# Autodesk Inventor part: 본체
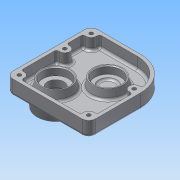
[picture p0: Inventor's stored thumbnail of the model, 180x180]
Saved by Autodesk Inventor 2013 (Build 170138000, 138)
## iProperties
Created: 2015-11
Part Number: 본체
Material: 알루미늄 6061
Document SubType Name: Modeling
Designer: Administrator
Density: 2.71 g/cm^3
Mass: 247.293 g
Surface Area: 390.248 cm^2
Volume: 91.2522 cm^3
Author: Administrator
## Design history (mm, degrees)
sketch "스케치1"
  geometry: L1 (-60, 40)-(-60, -63); L2 (-60, -63)-(40, -63); L3 (40, -63)-(40, 0); L4 (0, 40)-(-60, 40); A1 r 40 centre (0, 0) between (40, 0) and (0, 40); 1 further point
  constraints: 8 end point, 2 coincident, 2 parallel, 2 point on circle, 2 tangent, 1 centre point, 1 perpendicular, 1 vertical
  dimensions: "d0" = 103 distance between parallel lines of L2 L4; "d2" = 40 radius of A1; "d3" = 100 distance of L1.end L2.end
extrude "돌출1" new body sketch "스케치1" distance "d4" = 4; taper "d5" = 0 deg
fillet "모깎기1" dims "d6" = 8
sketch "스케치4"
  geometry: L1 (40, -55)-(40, 0) reference; L2 (0, 40)-(-52, 40) reference; L3 (-60, 32)-(-60, -55) reference; L4 (-52, -63)-(32, -63) reference; L5 (-47.528, 36)-(0, 36); L6 (36, -4.472)-(36, -50.528); L7 (27.528, -59)-(-47.528, -59); L8 (-56, -50.528)-(-56, -4.472); L9 (-56, 4.472)-(-56, 27.528); A1 r 8 centre (32, -55) between (32, -63) and (40, -55) reference; A2 r 40 centre (0, 0) between (40, 0) and (0, 40) reference; A3 r 8 centre (-52, 32) between (-52, 40) and (-60, 32) reference; A4 r 8 centre (-52, -55) between (-60, -55) and (-52, -63) reference; A5 r 36 centre (0, 0) between (35.688, 4.733) and (0, 36); A6 r 6 centre (-52, 32) between (-56, 27.528) and (-47.528, 36); A7 r 6 centre (-52, -55) between (-47.528, -59) and (-56, -50.528); A8 r 6 centre (-52, 0) between (-56, -4.472) and (-56, 4.472); A9 r 6 centre (32, 0) between (35.688, 4.733) and (36, -4.472); A10 r 6 centre (32, -55) between (36, -50.528) and (27.528, -59)
  constraints: 12 point on circle, 10 end point, 6 centre point, 4 coincident, 2 concentric, 2 horizontal alignment, 2 vertical alignment
  dimensions: "d17" = 4 distance between parallel lines of L2 L5; "d18" = 4 distance between parallel lines of L4 L7; "d20" = 12 diameter of A6; "d21" = 12 diameter of A7; "d22" = 12 diameter of A10; "d23" = 12 diameter of A9; "d24" = 12 diameter of A8; "d25" = 84 distance of A9.centre A8.centre; "d26" = 36 radius of A5; "d28" = 4 distance between parallel lines of L1 L6; "d29" = 4 distance between parallel lines of L3 L8; "d30" = 4 distance between parallel lines of L3 L9
extrude "돌출2" join sketch "스케치4" distance "d31" = 14; taper "d32" = 0 deg
sketch "스케치5"
  geometry: C1 r 20 at (0, 0); A1 r 36 centre (0, 0) between (35.688, 4.733) and (0, 36) reference
  constraints: 2 coincident, 1 centre point
  dimensions: "d33" = 40 diameter of C1
extrude "돌출3" join sketch "스케치5" distance "d35" = 11; taper "d36" = -10 deg
sketch "스케치7"
  geometry: C1 r 18.06 at (0, 0) reference; C2 r 16 at (0, 0)
  constraints: 2 coincident, 1 centre point
  dimensions: "d44" = 32 diameter of C2
extrude "돌출4" cut sketch "스케치7" distance "d46" = 9; taper "d47" = 0 deg
sketch "스케치8"
  geometry: C1 r 16 at (0, 0) reference; C2 r 11 at (0, 0)
  constraints: 1 centre point, 1 coincident
  dimensions: "d48" = 22 diameter of C2
extrude "돌출5" cut sketch "스케치8" distance "d50" = 2; taper "d51" = 0 deg
sketch "스케치10"
  geometry: L1 (52, -63)-(-32, -63) reference; L2 (60, 32)-(60, -55) reference; C1 r 25 at (30, -33)
  constraints: 1 centre point
  dimensions: "d55" = 30 distance from line of C1.centre L2; "d56" = 30 distance from line of L1 C1.centre; "d57" = 50 diameter of C1
extrude "돌출6" join sketch "스케치10" distance "d58" = 15; taper "d59" = -10 deg
sketch "스케치11"
  geometry: C1 r 22.355 at (0, 0) reference; 2 further points
  constraints: 1 coincident
hole "구멍2" sketch "스케치11" at (0, 0) diameter "d60" = 24; stored, may be unused: countersink angle "d64" = 90 deg, drill point angle "d66" = 0 deg; dims "d61" = 6, "d62" = 28, "d63" = 11, "d65" = 13
sketch "스케치13"
  geometry: L1 (-60, 32)-(-60, -55) reference; L2 (-52, -63)-(32, -63) reference; C1 r 20 at (-30, -33)
  constraints: 1 centre point
  dimensions: "d71" = 30 distance from line of L1 C1.centre; "d72" = 30 distance from line of C1.centre L2; "d73" = 40 diameter of C1
extrude "돌출8" join sketch "스케치13" distance "d74" = 11; taper "d75" = -10 deg
sketch "스케치16"
  geometry: C1 r 18.06 at (0, 0) reference; 2 further points
  constraints: 1 coincident
hole "구멍3" sketch "스케치16" at (0, 0) diameter "d79" = 20; stored, may be unused: countersink angle "d83" = 90 deg, drill point angle "d85" = 0 deg; dims "d80" = 6, "d81" = 32, "d82" = 9, "d84" = 20
sketch "스케치18"
  geometry: L1 (52, -63)-(-32, -63) reference; C1 r 4 at (52, 32); C2 r 4 at (52, 0); C3 r 4 at (52, -55); C4 r 4 at (-32, -55); C5 r 4 at (-32, 0); A1 r 8 centre (-32, -55) between (-40, -55) and (-32, -63) reference; A2 r 8 centre (52, 32) between (60, 32) and (52, 40) reference
  constraints: 5 centre point, 3 vertical alignment, 2 coincident, 1 horizontal alignment
  dimensions: "d88" = 8 diameter of C5; "d90" = 8 diameter of C4; "d91" = 8 diameter of C3; "d92" = 8 diameter of C2; "d93" = 8 diameter of C1; "d94" = 8 distance from line of C3.centre L1; "d95" = 63 distance from line of L1 C5.centre
extrude "돌출10" cut sketch "스케치18" distance "d96" = 4.4; taper "d97" = 0 deg
sketch "스케치19"
  geometry: C1 r 2.25 at (-52, 32); C2 r 2.25 at (-52, 0); C3 r 2.25 at (32, -55); C4 r 2.25 at (-52, -55); C5 r 2.25 at (32, 0); A1 r 6 centre (32, 0) between (35.688, 4.733) and (36, -4.472) reference; A2 r 6 centre (-52, 0) between (-56, -4.472) and (-56, 4.472) reference; A3 r 8 centre (32, -55) between (32, -63) and (40, -55) reference; A4 r 8 centre (-52, 32) between (-52, 40) and (-60, 32) reference; A5 r 8 centre (-52, -55) between (-60, -55) and (-52, -63) reference
  constraints: 5 centre point, 5 coincident
  dimensions: "d98" = 4.5 diameter of C1; "d100" = 4.5 diameter of C2; "d101" = 4.5 diameter of C4; "d102" = 4.5 diameter of C3; "d104" = 4.5 diameter of C5
extrude "돌출11" cut sketch "스케치19" stored distance "d105" = 4.4; taper "d106" = 0 deg
fillet "모깎기2" dims "d107" = 3
fillet "모깎기3" dims "d108" = 3
sketch "스케치21"
  geometry: L1 (-4.887, 23.602)-(44.887, 23.602); L2 (44.887, 23.602)-(44.887, 16.398); L3 (44.887, 16.398)-(-4.887, 16.398); L4 (-4.887, 16.398)-(-4.887, 23.602); L5 (-4.887, 20)-(44.887, 20); L6 (60, -27.689)-(60, 32) reference; L7 (52, 40)-(0, 40) reference; 2 further points
  constraints: 4 midpoint, 2 end point, 1 vertical alignment, 2 other
  dimensions: "d109" = 40 distance from line of L6 point (20, 20); "d110" = 20 distance from line of L7 point (20, 20)
feature "엠보싱1" sketch "스케치21" dims "d0" = 103, "d2" = 40, "d3" = 100, "d111" = 0.5, "d112" = 0
sketch "스케치22"
  geometry: C1 r 14 at (0, 0) reference; 2 further points
  constraints: 1 vertical alignment
  dimensions: "d113" = 18 distance of C1.centre point (0, 18)
hole "구멍4" sketch "스케치22" at (0, 18) diameter "d114" = 2.459; stored, may be unused: countersink angle "d118" = 90 deg, drill point angle "d120" = 118 deg; dims "d115" = 8, "d116" = 32, "d117" = 9, "d119" = 10
chamfer "모따기1" distance "d124" = 1; stored, may be unused: second distance "d125" = 2, angle "d126" = 45 deg
fillet "모깎기4" dims "d127" = 0.3
node "솔리드1"
pattern_circular "원형 패턴1" dims angle "d122" = 360 deg
other parameters: "d19" = 4
